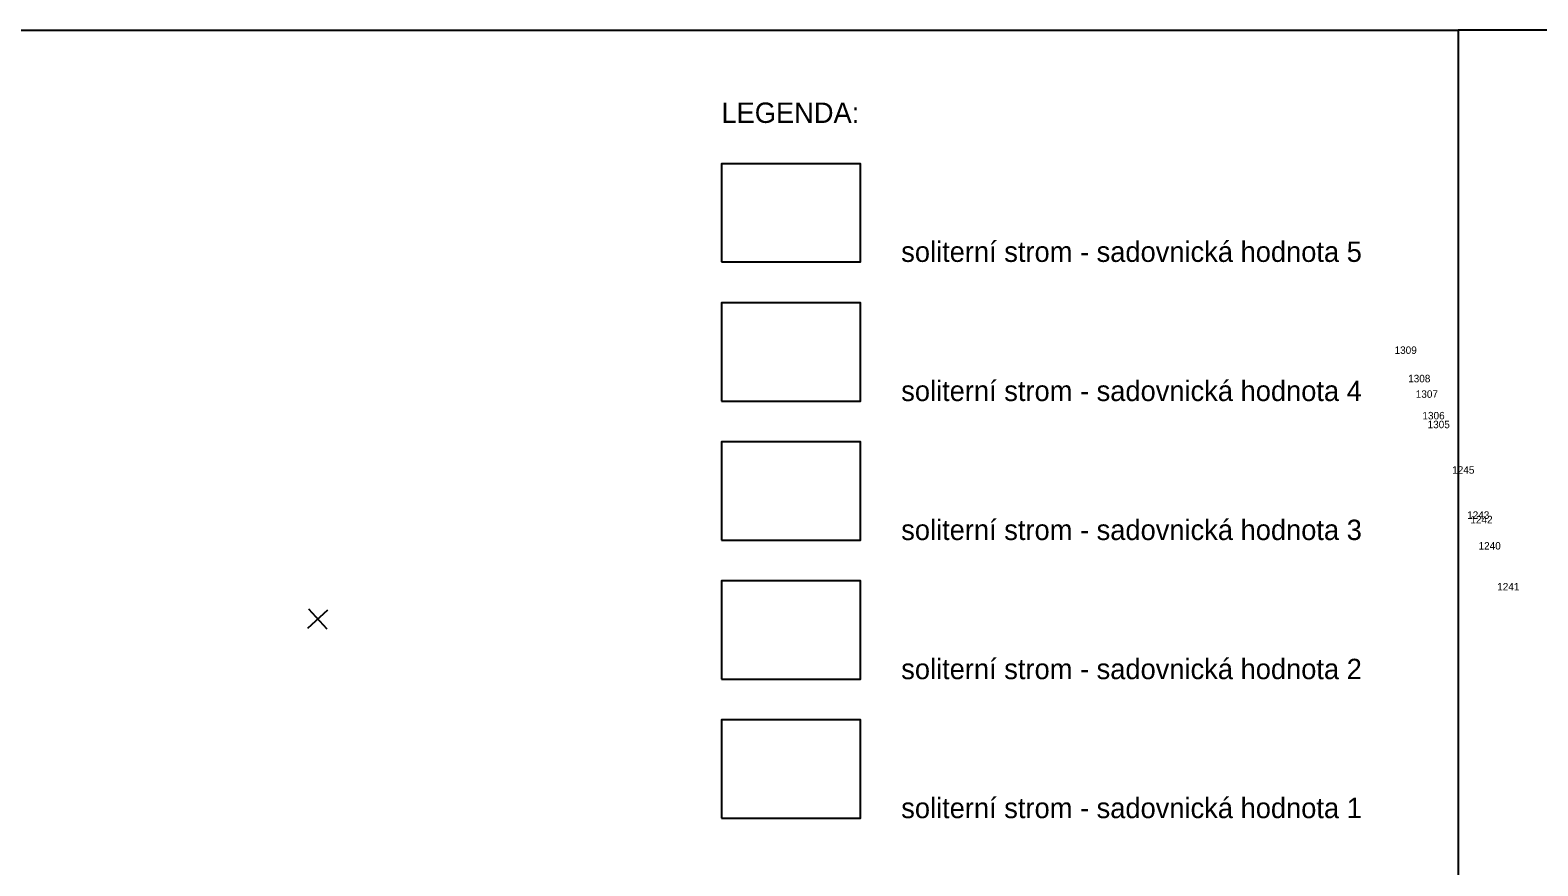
# Model space of a CAD drawing. Extents: x -740053 to -737481, y -1033516 to -1032488.
# Drawn here: x -737692.2 to -737581.2, y -1032868.3 to -1032806.8 of the extents above; entities that cross this region are included whole.
import ezdxf

# ---------------------------------------------------------------- set-up
doc = ezdxf.new("R2010")
doc.units = 0
for name, color, linetype in [('bod-cislo', 7, 'Continuous'), ('ctv-sit', 7, 'Continuous'), ('Predmety bez rozlišeni', 7, 'Continuous'), ('promika-formát', 7, 'Continuous')]:
    doc.layers.add(name, color=color, linetype=linetype)

# ---------------------------------------------------------------- blocks, each defined once
blk = doc.blocks.new('ctvsit')
for p, q in [((2, 0), (-2, 0)), ((0, -2), (0, 2))]:
    blk.add_line(p, q)

msp = doc.modelspace()

# ---------------------------------------------------------------- linework, layer by layer
at = {"layer": 'Predmety bez rozlišeni'}
for p, q in [((-737797.1, -1032806.76), (-737692.1, -1032806.76)), ((-737692.1, -1032806.76), (-737587.1, -1032806.76))]:
    msp.add_line(p, q, dxfattribs=at)
for points in [[(-737641.3, -1032823.82), (-737631.07, -1032823.82), (-737631.07, -1032816.59), (-737641.3, -1032816.59)], [(-737641.3, -1032834.06), (-737631.07, -1032834.06), (-737631.07, -1032826.82), (-737641.3, -1032826.82)], [(-737641.3, -1032844.29), (-737631.07, -1032844.29), (-737631.07, -1032837.06), (-737641.3, -1032837.06)], [(-737641.3, -1032854.53), (-737631.07, -1032854.53), (-737631.07, -1032847.29), (-737641.3, -1032847.29)], [(-737641.3, -1032864.76), (-737631.07, -1032864.76), (-737631.07, -1032857.53), (-737641.3, -1032857.53)]]:
    msp.add_lwpolyline(points, close=True, dxfattribs=at)
at = {"layer": 'promika-formát'}
msp.add_lwpolyline([(-737587.1, -1032955.26), (-737482.1, -1032955.26), (-737482.1, -1032806.76), (-737587.1, -1032806.76)], close=True, dxfattribs=at)

# ---------------------------------------------------------------- block references
at = {"layer": 'ctv-sit', "xscale": 0.49999999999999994, "yscale": 0.49999999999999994, "rotation": -137.41057066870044}
msp.add_blockref('ctvsit', (-737671, -1032850.1), dxfattribs=at)

# ---------------------------------------------------------------- texts
at = {"layer": 'bod-cislo'}
for s, p in [('1309', (-737591.77, -1032830.59)), ('1308', (-737590.77, -1032832.68)), ('1307', (-737590.21, -1032833.82)), ('1306', (-737589.72, -1032835.41)), ('1305', (-737589.34, -1032836.06)), ('1245', (-737587.53, -1032839.41)), ('1243', (-737586.43, -1032842.73)), ('1242', (-737586.19, -1032843.06)), ('1240', (-737585.59, -1032844.99)), ('1241', (-737584.22, -1032848))]:
    msp.add_text(s, height=0.55, dxfattribs=at).set_placement(p)
at = {"layer": 'Predmety bez rozlišeni'}
for s, p in [('LEGENDA:', (-737641.3, -1032813.59)), ('soliterní strom - sadovnická hodnota 5', (-737628.07, -1032823.82)), ('soliterní strom - sadovnická hodnota 4', (-737628.07, -1032834.06)), ('soliterní strom - sadovnická hodnota 3', (-737628.07, -1032844.29)), ('soliterní strom - sadovnická hodnota 2 ', (-737628.07, -1032854.53)), ('soliterní strom - sadovnická hodnota 1', (-737628.07, -1032864.76))]:
    msp.add_text(s, height=1.5, dxfattribs=at).set_placement(p)

doc.saveas('drawing.dxf')
